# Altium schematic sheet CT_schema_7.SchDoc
size 372 x 245 mm
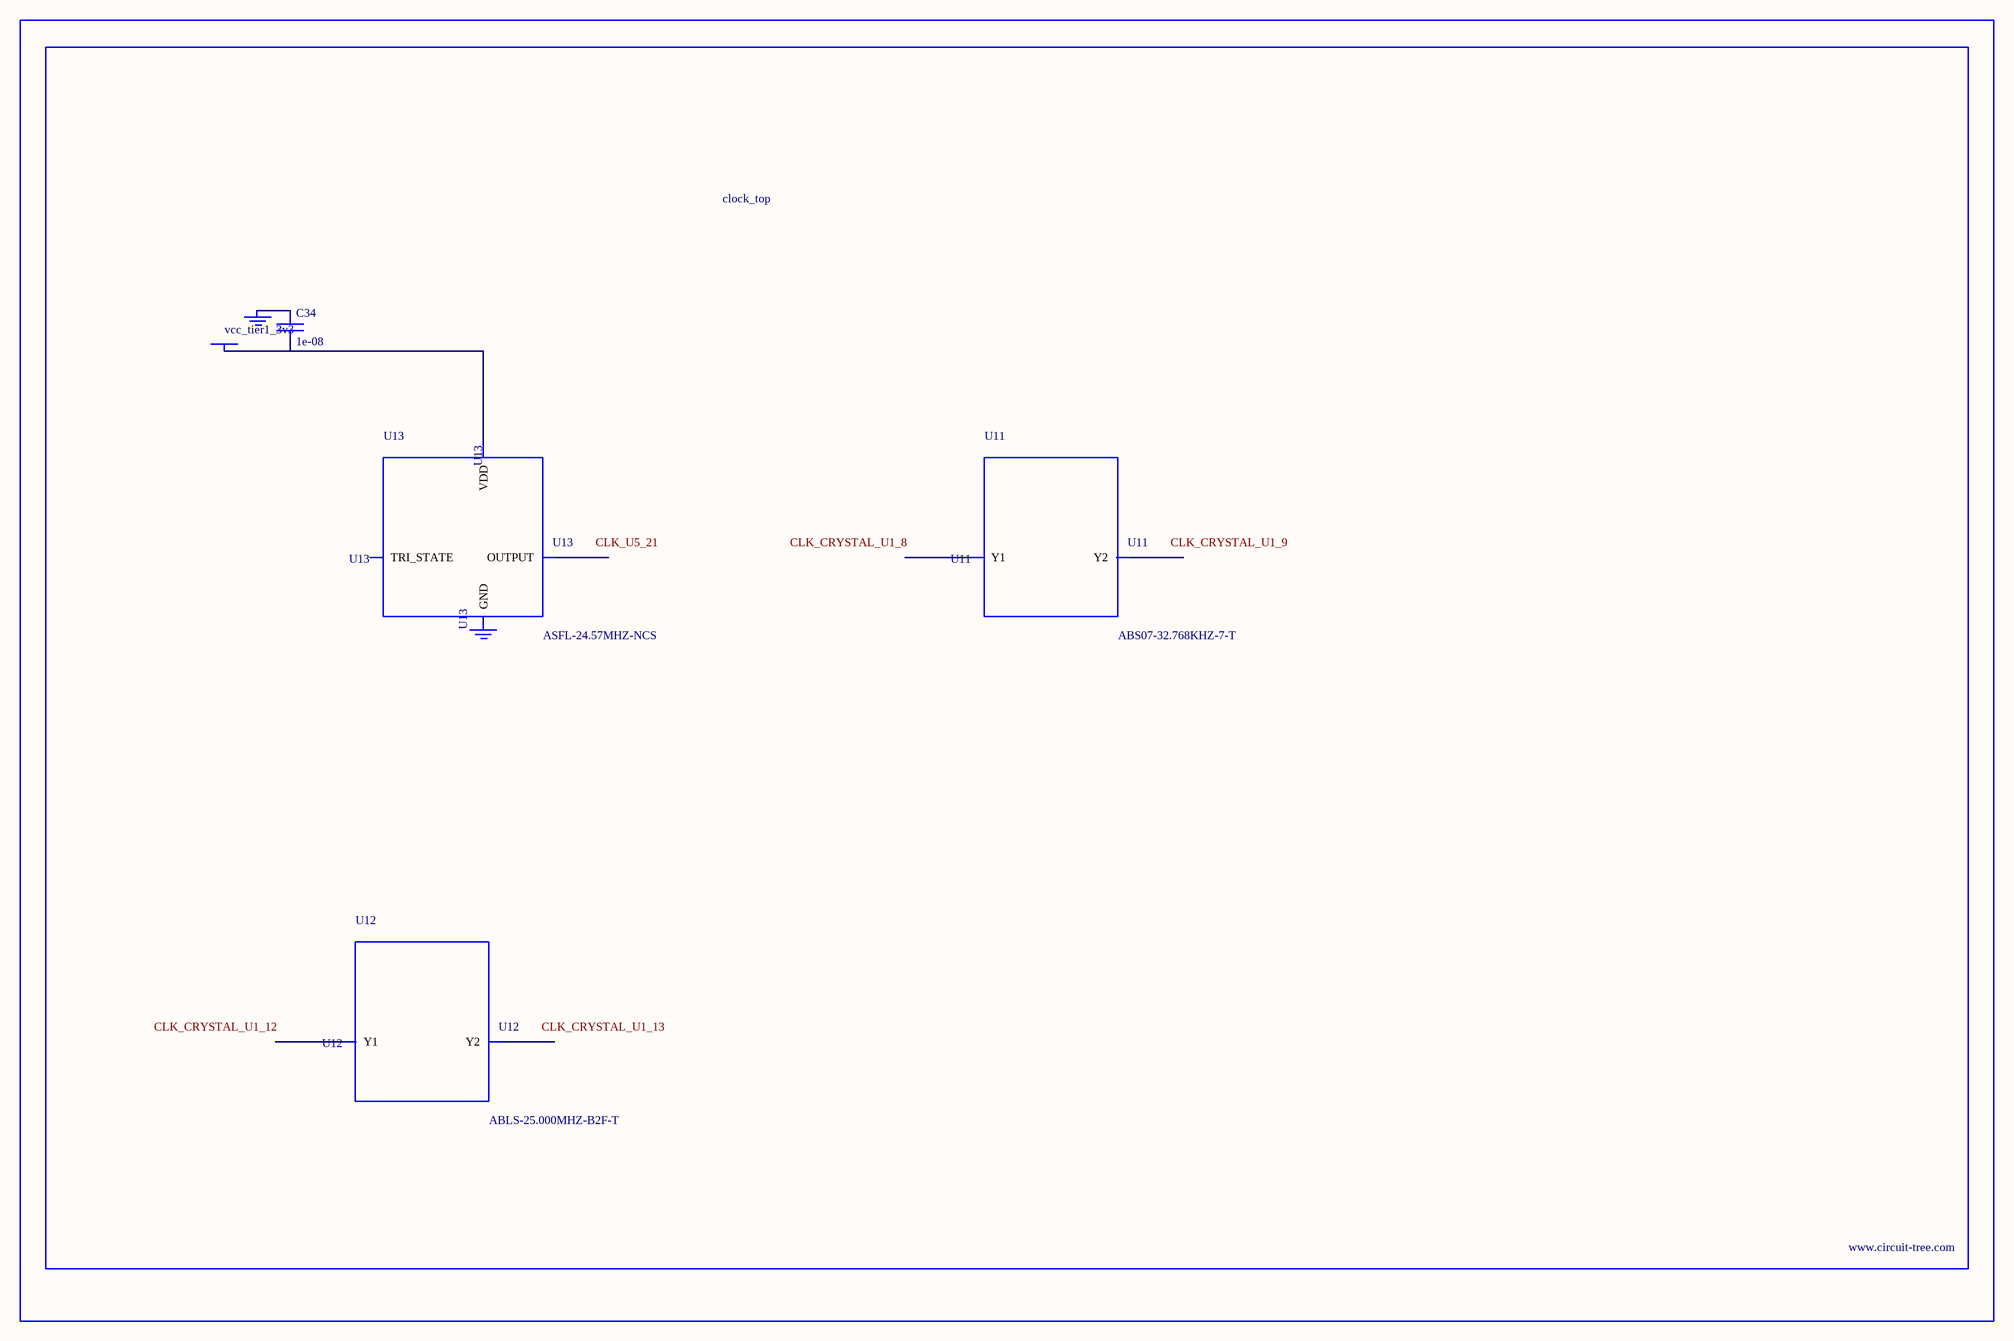
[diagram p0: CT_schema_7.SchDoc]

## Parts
BORDER6  (no value)
C34  1e-08  [C0402]
GND_INSTANCE_6_0  (no value)
GND_INSTANCE_6_1  (no value)
POWER_INSTANCE_6_0  vcc_tier1_3v3
U11  ABS07-32.768KHZ-7-T  [ABS07-32.768KHZ-7-T]
U12  ABLS-25.000MHZ-B2F-T  [ABLS-25.000MHZ-B2F-T]
U13  ASFL-24.57MHZ-NCS  [ASFL1]

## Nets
NetC34_1: C34.1 GND_INSTANCE_6_0.0(GND)
NetC34_2: C34.2 POWER_INSTANCE_6_0.0(PWR) U13.4(VDD)

Not connected (* = marked no-connect by the designer): GND_INSTANCE_6_1 0(GND); U11 1(Y1) 2(Y2); U12 1(Y1) 2(Y2); U13 1(TRI_STATE) 2(GND) 3(OUTPUT)

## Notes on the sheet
- Labels drawn without touching a wire or pin: CLK_CRYSTAL_U1_8, CLK_CRYSTAL_U1_9, CLK_CRYSTAL_U1_12, CLK_CRYSTAL_U1_13, CLK_U5_21

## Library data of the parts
BORDER6 = BORDER_PAGE6
C34 = C0402C103K3RAC
GND_INSTANCE_6_0 GND_INSTANCE_6_1 = GND
POWER_INSTANCE_6_0 = PWR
